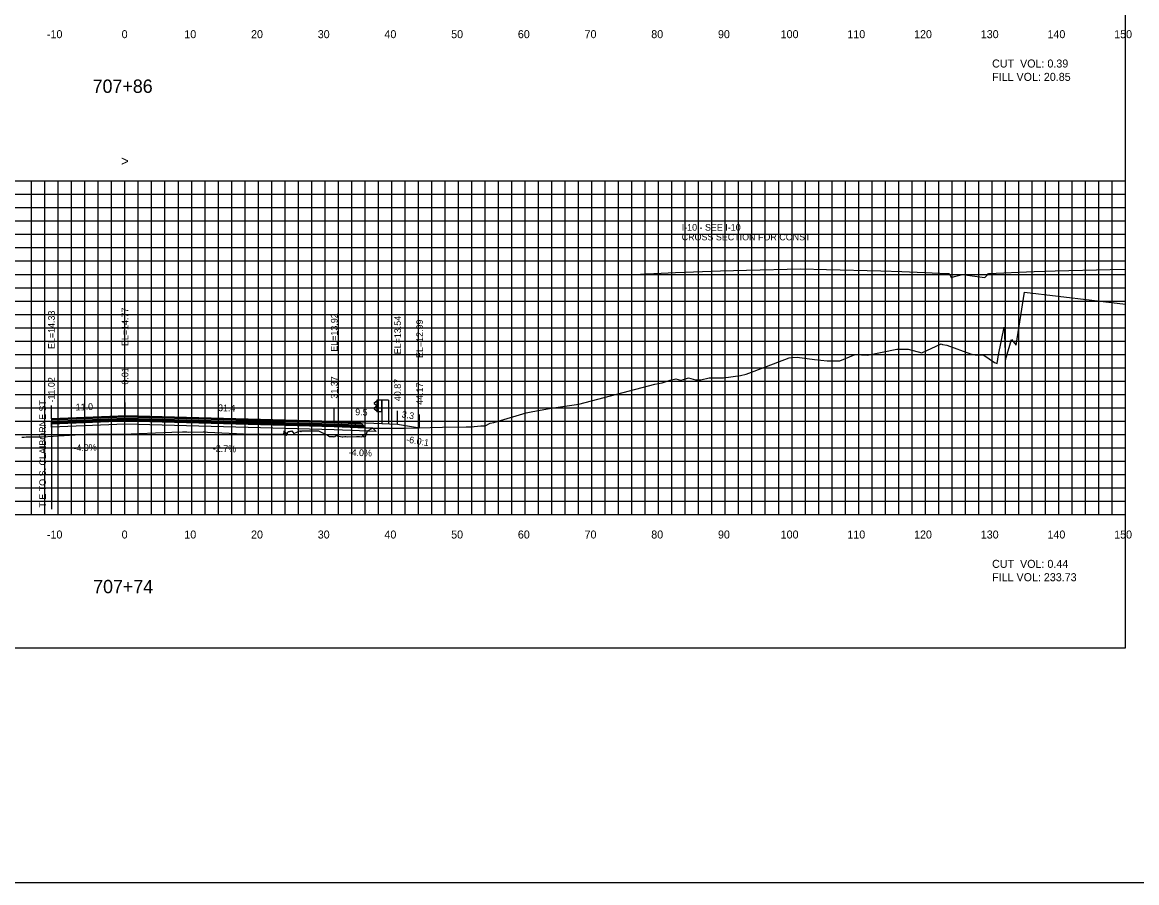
# Model space of a CAD drawing. Extents: x 1797518 to 1804843, y 248068 to 251132.
# Drawn here: x 1804315.6 to 1804482.7, y 250044.2 to 250173.2 of the extents above; entities that cross this region are included whole.
import ezdxf

# ---------------------------------------------------------------- set-up
doc = ezdxf.new("R2010")
doc.units = 0
for name, color, linetype in [('1', 7, 'Continuous'), ('10', 7, 'Continuous'), ('3', 7, 'Continuous'), ('4', 7, 'Continuous'), ('60', 7, 'Continuous'), ('ANNO-TXT', 7, 'Continuous'), ('BASE', 7, 'Continuous'), ('CL-CNST', 7, 'Continuous'), ('Level 1', 7, 'Continuous'), ('Level 62', 7, 'Continuous'), ('LOWER BINDER', 7, 'Continuous'), ('M-ROADS', 7, 'Continuous'), ('UPPER BINDER', 7, 'Continuous'), ('WEARING', 7, 'Continuous')]:
    doc.layers.add(name, color=color, linetype=linetype)

msp = doc.modelspace()

# ---------------------------------------------------------------- linework, layer by layer
for p, q in [((1804319.98, 250113.76), (1804319.98, 250115.76)), ((1804331.01, 250114.2), (1804331.01, 250116.2)), ((1804362.37, 250113.35), (1804362.37, 250115.35)), ((1804371.87, 250112.97), (1804371.87, 250114.97)), ((1804375.17, 250112.42), (1804375.17, 250114.42))]:
    msp.add_line(p, q)
msp.add_lwpolyline([(1804181, 250079.43), (1804481, 250079.43), (1804481, 250269.43), (1804181, 250269.43)], close=True)
at = {"layer": '1'}
msp.add_lwpolyline([(1804164.33, 250290.86), (1804501.93, 250290.86), (1804501.93, 250044.24), (1804164.33, 250044.24)], close=True, dxfattribs=at)
at = {"layer": '3'}
msp.add_line((1804319.97, 250113.76), (1804319.97, 250100.21), dxfattribs=at)
at = {"layer": '60'}
for p, q in [((1804481, 250099.43), (1804481, 250149.43)), ((1804481.06, 250149.43), (1804481, 250149.43)), ((1804481.06, 250139.43), (1804481, 250139.43)), ((1804481.06, 250129.43), (1804481, 250129.43)), ((1804481.06, 250119.43), (1804481, 250119.43)), ((1804481.06, 250109.43), (1804481, 250109.43)), ((1804181, 250099.43), (1804481, 250099.43)), ((1804321, 250099.37), (1804321, 250099.43)), ((1804331, 250099.37), (1804331, 250099.43)), ((1804341, 250099.37), (1804341, 250099.43)), ((1804351, 250099.37), (1804351, 250099.43)), ((1804361, 250099.37), (1804361, 250099.43)), ((1804371, 250099.37), (1804371, 250099.43)), ((1804381, 250099.37), (1804381, 250099.43)), ((1804391, 250099.37), (1804391, 250099.43)), ((1804401, 250099.37), (1804401, 250099.43)), ((1804411, 250099.37), (1804411, 250099.43)), ((1804421, 250099.37), (1804421, 250099.43)), ((1804431, 250099.37), (1804431, 250099.43)), ((1804441, 250099.37), (1804441, 250099.43)), ((1804451, 250099.37), (1804451, 250099.43)), ((1804461, 250099.37), (1804461, 250099.43)), ((1804471, 250099.37), (1804471, 250099.43)), ((1804481, 250099.37), (1804481, 250099.43)), ((1804481.06, 250099.43), (1804481, 250099.43))]:
    msp.add_line(p, q, dxfattribs=at)
at = {"layer": 'BASE'}
msp.add_lwpolyline([(1804319.98, 250113.04), (1804331.01, 250113.48), (1804362.37, 250112.63), (1804367.12, 250112.44), (1804368.12, 250112.4), (1804368.64, 250111.88), (1804362.37, 250112.13), (1804331.01, 250112.98), (1804319.98, 250112.54)], close=True, dxfattribs=at)
at = {"layer": 'CL-CNST'}
for points in [[(1804404.8, 250135.34), (1804405.94, 250135.39), (1804408.3, 250135.48), (1804408.95, 250135.51), (1804410.3, 250135.56), (1804413.55, 250135.69), (1804420.3, 250135.96), (1804424.18, 250136.05), (1804432.3, 250136.23), (1804436.15, 250136.14), (1804444.3, 250135.97), (1804447.48, 250135.84), (1804454.3, 250135.57), (1804454.38, 250135.56), (1804454.55, 250135.56), (1804454.64, 250135.37), (1804454.84, 250134.96), (1804455.38, 250135.1), (1804456.55, 250135.41), (1804458.77, 250135.1), (1804459.92, 250134.96), (1804460.29, 250135.37), (1804460.46, 250135.57), (1804467.32, 250135.84), (1804470.46, 250135.97), (1804478.72, 250136.15), (1804481, 250136.2)], [(1804319.98, 250113.76), (1804331.01, 250114.2), (1804362.37, 250113.35), (1804371.87, 250112.97), (1804375.17, 250112.42)]]:
    msp.add_lwpolyline(points, dxfattribs=at)
at = {"layer": 'Level 1'}
for p, q in [((1804368.74, 250116.44), (1804368.37, 250116.14)), ((1804368.37, 250116.07), (1804368.74, 250115.79)), ((1804368.74, 250115.65), (1804368.37, 250115.35)), ((1804368.37, 250115.28), (1804368.74, 250114.99)), ((1804368.74, 250116.59), (1804368.74, 250114.84)), ((1804370.49, 250116.59), (1804368.74, 250116.59)), ((1804368.79, 250116.59), (1804368.79, 250114.84)), ((1804369.44, 250116.59), (1804369.44, 250114.84)), ((1804369.49, 250116.59), (1804369.49, 250113.07)), ((1804370.49, 250116.59), (1804370.49, 250113.03)), ((1804369.49, 250114.84), (1804368.74, 250114.84))]:
    msp.add_line(p, q, dxfattribs=at)
for centre in [(1804368.41, 250116.11), (1804368.41, 250115.31)]:
    msp.add_arc(centre, 0.05, 135, 226.6208, dxfattribs=at)
at = {"layer": 'Level 62'}
for p, q in [((1804181, 250149.43), (1804481, 250149.43)), ((1804317, 250099.43), (1804317, 250149.43)), ((1804319, 250099.43), (1804319, 250149.43)), ((1804321, 250099.43), (1804321, 250149.43)), ((1804323, 250099.43), (1804323, 250149.43)), ((1804325, 250099.43), (1804325, 250149.43)), ((1804327, 250099.43), (1804327, 250149.43)), ((1804329, 250099.43), (1804329, 250149.43)), ((1804331, 250099.43), (1804331, 250149.43)), ((1804333, 250099.43), (1804333, 250149.43)), ((1804335, 250099.43), (1804335, 250149.43)), ((1804337, 250099.43), (1804337, 250149.43)), ((1804339, 250099.43), (1804339, 250149.43)), ((1804341, 250099.43), (1804341, 250149.43)), ((1804343, 250099.43), (1804343, 250149.43)), ((1804345, 250099.43), (1804345, 250149.43)), ((1804347, 250099.43), (1804347, 250149.43)), ((1804349, 250099.43), (1804349, 250149.43)), ((1804351, 250099.43), (1804351, 250149.43)), ((1804353, 250099.43), (1804353, 250149.43)), ((1804355, 250099.43), (1804355, 250149.43)), ((1804357, 250099.43), (1804357, 250149.43)), ((1804359, 250099.43), (1804359, 250149.43)), ((1804361, 250099.43), (1804361, 250149.43)), ((1804363, 250099.43), (1804363, 250149.43)), ((1804365, 250099.43), (1804365, 250149.43)), ((1804367, 250099.43), (1804367, 250149.43)), ((1804369, 250099.43), (1804369, 250149.43)), ((1804371, 250099.43), (1804371, 250149.43)), ((1804373, 250099.43), (1804373, 250149.43)), ((1804375, 250099.43), (1804375, 250149.43)), ((1804377, 250099.43), (1804377, 250149.43)), ((1804379, 250099.43), (1804379, 250149.43)), ((1804381, 250099.43), (1804381, 250149.43)), ((1804383, 250099.43), (1804383, 250149.43)), ((1804385, 250099.43), (1804385, 250149.43)), ((1804387, 250099.43), (1804387, 250149.43)), ((1804389, 250099.43), (1804389, 250149.43)), ((1804391, 250099.43), (1804391, 250149.43)), ((1804393, 250099.43), (1804393, 250149.43)), ((1804395, 250099.43), (1804395, 250149.43)), ((1804397, 250099.43), (1804397, 250149.43)), ((1804399, 250099.43), (1804399, 250149.43)), ((1804401, 250099.43), (1804401, 250149.43)), ((1804403, 250099.43), (1804403, 250149.43)), ((1804405, 250099.43), (1804405, 250149.43)), ((1804407, 250099.43), (1804407, 250149.43)), ((1804409, 250099.43), (1804409, 250149.43)), ((1804411, 250099.43), (1804411, 250149.43)), ((1804413, 250099.43), (1804413, 250149.43)), ((1804415, 250099.43), (1804415, 250149.43)), ((1804417, 250099.43), (1804417, 250149.43)), ((1804419, 250099.43), (1804419, 250149.43)), ((1804421, 250099.43), (1804421, 250149.43)), ((1804423, 250099.43), (1804423, 250149.43)), ((1804425, 250099.43), (1804425, 250149.43)), ((1804427, 250099.43), (1804427, 250149.43)), ((1804429, 250099.43), (1804429, 250149.43)), ((1804431, 250099.43), (1804431, 250149.43)), ((1804433, 250099.43), (1804433, 250149.43)), ((1804435, 250099.43), (1804435, 250149.43)), ((1804437, 250099.43), (1804437, 250149.43)), ((1804439, 250099.43), (1804439, 250149.43)), ((1804441, 250099.43), (1804441, 250149.43)), ((1804443, 250099.43), (1804443, 250149.43)), ((1804445, 250099.43), (1804445, 250149.43)), ((1804447, 250099.43), (1804447, 250149.43)), ((1804449, 250099.43), (1804449, 250149.43)), ((1804451, 250099.43), (1804451, 250149.43)), ((1804453, 250099.43), (1804453, 250149.43)), ((1804455, 250099.43), (1804455, 250149.43)), ((1804457, 250099.43), (1804457, 250149.43)), ((1804459, 250099.43), (1804459, 250149.43)), ((1804461, 250099.43), (1804461, 250149.43)), ((1804463, 250099.43), (1804463, 250149.43)), ((1804465, 250099.43), (1804465, 250149.43)), ((1804467, 250099.43), (1804467, 250149.43)), ((1804469, 250099.43), (1804469, 250149.43)), ((1804471, 250099.43), (1804471, 250149.43)), ((1804473, 250099.43), (1804473, 250149.43)), ((1804475, 250099.43), (1804475, 250149.43)), ((1804477, 250099.43), (1804477, 250149.43)), ((1804479, 250099.43), (1804479, 250149.43)), ((1804481, 250099.43), (1804481, 250149.43)), ((1804181, 250147.43), (1804481, 250147.43)), ((1804181, 250145.43), (1804481, 250145.43)), ((1804181, 250143.43), (1804481, 250143.43)), ((1804181, 250141.43), (1804481, 250141.43)), ((1804181, 250139.43), (1804481, 250139.43)), ((1804181, 250137.43), (1804481, 250137.43)), ((1804181, 250135.43), (1804481, 250135.43)), ((1804181, 250133.43), (1804481, 250133.43)), ((1804181, 250131.43), (1804481, 250131.43)), ((1804181, 250129.43), (1804481, 250129.43)), ((1804181, 250127.43), (1804481, 250127.43)), ((1804181, 250125.43), (1804481, 250125.43)), ((1804181, 250123.43), (1804481, 250123.43)), ((1804181, 250121.43), (1804481, 250121.43)), ((1804181, 250119.43), (1804481, 250119.43)), ((1804181, 250117.43), (1804481, 250117.43)), ((1804181, 250115.43), (1804481, 250115.43)), ((1804181, 250113.43), (1804481, 250113.43)), ((1804181, 250111.43), (1804481, 250111.43)), ((1804181, 250109.43), (1804481, 250109.43)), ((1804181, 250107.43), (1804481, 250107.43)), ((1804181, 250105.43), (1804481, 250105.43)), ((1804181, 250103.43), (1804481, 250103.43)), ((1804181, 250101.43), (1804481, 250101.43)), ((1804181, 250099.43), (1804481, 250099.43))]:
    msp.add_line(p, q, dxfattribs=at)
at = {"layer": 'LOWER BINDER'}
for points in [[(1804331.01, 250113.86), (1804362.37, 250113.01), (1804366.72, 250112.84), (1804366.92, 250112.64), (1804362.37, 250112.82), (1804331.01, 250113.67), (1804319.98, 250113.23), (1804319.98, 250113.42)], [(1804331.01, 250113.67), (1804362.37, 250112.82), (1804366.92, 250112.64), (1804367.12, 250112.44), (1804362.37, 250112.63), (1804331.01, 250113.48), (1804319.98, 250113.04), (1804319.98, 250113.23)]]:
    msp.add_lwpolyline(points, close=True, dxfattribs=at)
at = {"layer": 'M-ROADS'}
msp.add_lwpolyline([(1804315.53, 250111.01), (1804315.77, 250111.02), (1804315.89, 250111.02), (1804316.21, 250111.06), (1804318.6, 250111.05), (1804318.6, 250111.05), (1804318.61, 250111.05), (1804325.2, 250111.45), (1804325.42, 250111.45), (1804327.05, 250111.46), (1804327.68, 250111.46), (1804327.97, 250111.45), (1804330.15, 250111.46), (1804330.29, 250111.46), (1804330.37, 250111.46), (1804330.42, 250111.47), (1804330.7, 250111.48), (1804338, 250111.79), (1804339.6, 250111.82), (1804340.26, 250111.82), (1804340.54, 250111.79), (1804342.71, 250111.8), (1804342.86, 250111.8), (1804342.94, 250111.8), (1804343.36, 250111.78), (1804349.88, 250111.48), (1804351.15, 250111.5), (1804352.25, 250111.48), (1804352.4, 250111.47), (1804353.51, 250111.47), (1804354.37, 250111.48), (1804354.8, 250111.45), (1804354.83, 250111.48), (1804354.86, 250111.86), (1804354.87, 250111.89), (1804354.87, 250111.95), (1804354.96, 250111.3), (1804355, 250111.32), (1804355.01, 250111.34), (1804355.01, 250111.37), (1804355.02, 250111.45), (1804355.04, 250111.78), (1804355.15, 250111.66), (1804355.17, 250111.33), (1804355.22, 250111.29), (1804355.34, 250111.63), (1804355.47, 250111.87), (1804355.7, 250111.87), (1804355.71, 250111.93), (1804355.96, 250111.94), (1804356.02, 250111.96), (1804356.33, 250111.58), (1804357.2, 250111.97), (1804357.34, 250111.84), (1804357.47, 250111.97), (1804358.87, 250111.97), (1804360, 250111.97), (1804361.37, 250111.31), (1804361.66, 250111.1), (1804362.26, 250111.11), (1804362.27, 250111.09), (1804362.47, 250111.14), (1804362.73, 250111.33), (1804362.81, 250111.23), (1804363.57, 250111.09), (1804363.68, 250111.08), (1804363.97, 250111.11), (1804364.1, 250111.1), (1804364.33, 250111.08), (1804365.73, 250111.11), (1804365.98, 250111.1), (1804366.14, 250111.1), (1804366.48, 250111.08), (1804366.62, 250111.14), (1804366.66, 250111.33), (1804366.71, 250111.17), (1804366.79, 250111.05), (1804367.06, 250111.12), (1804367.35, 250111.98), (1804368.12, 250112.35), (1804368.14, 250112.36), (1804368.19, 250112.36), (1804370.66, 250112.36), (1804372.53, 250112.36), (1804373.05, 250112.36), (1804378.59, 250112.52), (1804382.13, 250112.56), (1804382.4, 250112.59), (1804382.55, 250112.56), (1804382.85, 250112.59), (1804384.33, 250112.72), (1804384.99, 250112.72), (1804385.76, 250113.1), (1804386.31, 250113.22), (1804391.17, 250114.67), (1804391.91, 250114.81), (1804394.91, 250115.39), (1804399.06, 250115.99), (1804410.42, 250118.96), (1804411.53, 250119.16), (1804412.75, 250119.55), (1804413.57, 250119.75), (1804414.3, 250119.55), (1804414.72, 250119.68), (1804415.49, 250119.91), (1804416.53, 250119.63), (1804417.31, 250119.6), (1804418.57, 250119.91), (1804420.72, 250119.91), (1804423.3, 250120.27), (1804424.14, 250120.49), (1804427.17, 250121.63), (1804430.56, 250122.9), (1804430.95, 250122.94), (1804431.77, 250123.02), (1804434.39, 250122.68), (1804436.25, 250122.44), (1804437.35, 250122.44), (1804438.18, 250122.44), (1804440.48, 250123.42), (1804442.32, 250123.3), (1804446.73, 250124.21), (1804447.45, 250124.21), (1804448.4, 250124.21), (1804450.48, 250123.68), (1804453.37, 250125.02), (1804453.56, 250124.91), (1804454.19, 250124.81), (1804457.75, 250123.51), (1804458.46, 250123.34), (1804459.77, 250123.32), (1804461.36, 250122.22), (1804461.77, 250122.06), (1804461.96, 250123.37), (1804462.79, 250127.5), (1804463.02, 250122.63), (1804463.93, 250125.66), (1804464.62, 250124.79), (1804465.84, 250132.76), (1804481, 250130.98)], dxfattribs=at)
at = {"layer": 'UPPER BINDER'}
msp.add_lwpolyline([(1804366.72, 250112.84), (1804366.52, 250113.04), (1804362.37, 250113.2), (1804331.01, 250114.05), (1804319.98, 250113.61), (1804319.98, 250113.42), (1804331.01, 250113.86), (1804362.37, 250113.01)], close=True, dxfattribs=at)
at = {"layer": 'WEARING'}
msp.add_lwpolyline([(1804366.52, 250113.04), (1804366.37, 250113.19), (1804362.37, 250113.35), (1804331.01, 250114.2), (1804329.98, 250114.16), (1804319.98, 250113.76), (1804319.98, 250113.61), (1804331.01, 250114.05), (1804362.37, 250113.2)], close=True, dxfattribs=at)

# ---------------------------------------------------------------- texts
msp.add_text('-6.0:1', height=1, rotation=350.5358).set_placement((1804373.11, 250110.23))
at = {"layer": '1'}
for s, p in [('707+86', (1804326.15, 250162.63)), ('707+74', (1804326.23, 250087.63))]:
    msp.add_text(s, height=2, dxfattribs=at).set_placement(p)
at = {"layer": '10'}
for s, p in [('-10', (1804319.3, 250170.83)), ('0', (1804330.5, 250170.83)), ('10', (1804339.9, 250170.83)), ('20', (1804349.9, 250170.83)), ('30', (1804359.9, 250170.83)), ('40', (1804369.9, 250170.83)), ('50', (1804379.9, 250170.83)), ('60', (1804389.9, 250170.83)), ('70', (1804399.9, 250170.83)), ('80', (1804409.9, 250170.83)), ('90', (1804419.9, 250170.83)), ('100', (1804429.3, 250170.83)), ('110', (1804439.3, 250170.83)), ('120', (1804449.3, 250170.83)), ('130', (1804459.3, 250170.83)), ('140', (1804469.3, 250170.83)), ('150', (1804479.3, 250170.83)), ('-10', (1804319.3, 250095.83)), ('0', (1804330.5, 250095.83)), ('10', (1804339.9, 250095.83)), ('20', (1804349.9, 250095.83)), ('30', (1804359.9, 250095.83)), ('40', (1804369.9, 250095.83)), ('50', (1804379.9, 250095.83)), ('60', (1804389.9, 250095.83)), ('70', (1804399.9, 250095.83)), ('80', (1804409.9, 250095.83)), ('90', (1804419.9, 250095.83)), ('100', (1804429.3, 250095.83)), ('110', (1804439.3, 250095.83)), ('120', (1804449.3, 250095.83)), ('130', (1804459.3, 250095.83)), ('140', (1804469.3, 250095.83)), ('150', (1804479.3, 250095.83))]:
    msp.add_text(s, height=1.2, dxfattribs=at).set_placement(p)
at = {"layer": '3'}
for s, p in [('I-10 - SEE I-10', (1804414.46, 250141.97)), ('CROSS SECTION FOR CONST ', (1804414.46, 250140.53))]:
    msp.add_text(s, height=1, dxfattribs=at).set_placement(p)
for s, p in [('EL=14.77', (1804331.51, 250124.68)), ('EL=14.33', (1804320.48, 250124.23)), ('EL=13.92', (1804362.87, 250123.83)), ('EL=13.54', (1804372.37, 250123.45)), ('EL=12.99', (1804375.67, 250122.89)), ('0.01', (1804331.51, 250118.9)), ('31.37', (1804362.87, 250116.8)), ('-11.02', (1804320.48, 250116.22)), ('40.87', (1804372.37, 250116.42)), ('44.17', (1804375.67, 250115.87)), ('TIE TO S. CLAIBORNE ST', (1804319.15, 250100.46))]:
    msp.add_text(s, height=1, rotation=90, dxfattribs=at).set_placement(p)
at = {"layer": '4'}
for s, rotation, p in [('11.0', 2.2896, (1804323.63, 250115.01)), ('31.4', 358.4467, (1804344.94, 250114.93)), ('9.5', 357.7094, (1804365.5, 250114.31)), ('3.3', 350.5358, (1804372.43, 250113.99)), ('-4.0%', 2.2896, (1804323.29, 250108.89)), ('-2.7%', 358.4467, (1804344.15, 250108.85)), ('-4.0%', 357.7094, (1804364.51, 250108.26))]:
    msp.add_text(s, height=1, rotation=rotation, dxfattribs=at).set_placement(p)
at = {"layer": '60'}
msp.add_text('>', height=1.5, dxfattribs=at).set_placement((1804330.39, 250151.68))
at = {"layer": 'ANNO-TXT'}
for s, p in [('CUT  VOL: 0.39', (1804461, 250166.43)), ('FILL VOL: 20.85', (1804461, 250164.43)), ('CUT  VOL: 0.44', (1804461, 250091.43)), ('FILL VOL: 233.73', (1804461, 250089.43))]:
    msp.add_text(s, height=1.2, dxfattribs=at).set_placement(p)

doc.saveas('drawing.dxf')
